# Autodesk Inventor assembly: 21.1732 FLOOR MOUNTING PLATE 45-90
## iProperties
Created: 2007-04
Part Number: 21.1732 FLOOR MOUNTING PLATE 45-90
Document SubType Name: Assembly
Designer: Andy Moles
Author: Andy Moles
